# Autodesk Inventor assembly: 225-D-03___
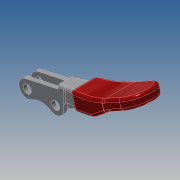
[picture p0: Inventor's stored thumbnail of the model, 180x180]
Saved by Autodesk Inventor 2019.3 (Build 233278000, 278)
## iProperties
Created: 2010-06
Part Number: 225-D-03___
Material: Ogólny
Document SubType Name: Assembly
Designer: CADENGINEERING4
Author: CADENGINEERING4
Revision Number: ANY
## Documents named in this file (3)
- E:\STRONA\Horizontal toggle clamp\CH-225-DI\225-D-03___.iam
- E:\STRONA\Horizontal toggle clamp\CH-225-DI\225-D-03___.ipt
- E:\STRONA\Horizontal toggle clamp\CH-225-DI\1___.ipt
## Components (2 placed, 2 different names)
1. 225-D-03_??_15
2. 1_??_16
